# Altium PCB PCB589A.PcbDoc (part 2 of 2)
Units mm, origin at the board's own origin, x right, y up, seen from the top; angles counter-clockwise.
Board outline 111 x 86 mm, 2 copper layers (Top Layer, Top, Bottom Layer, Bottom); 127 components, 84 nets, 406 pads, 157 vias.
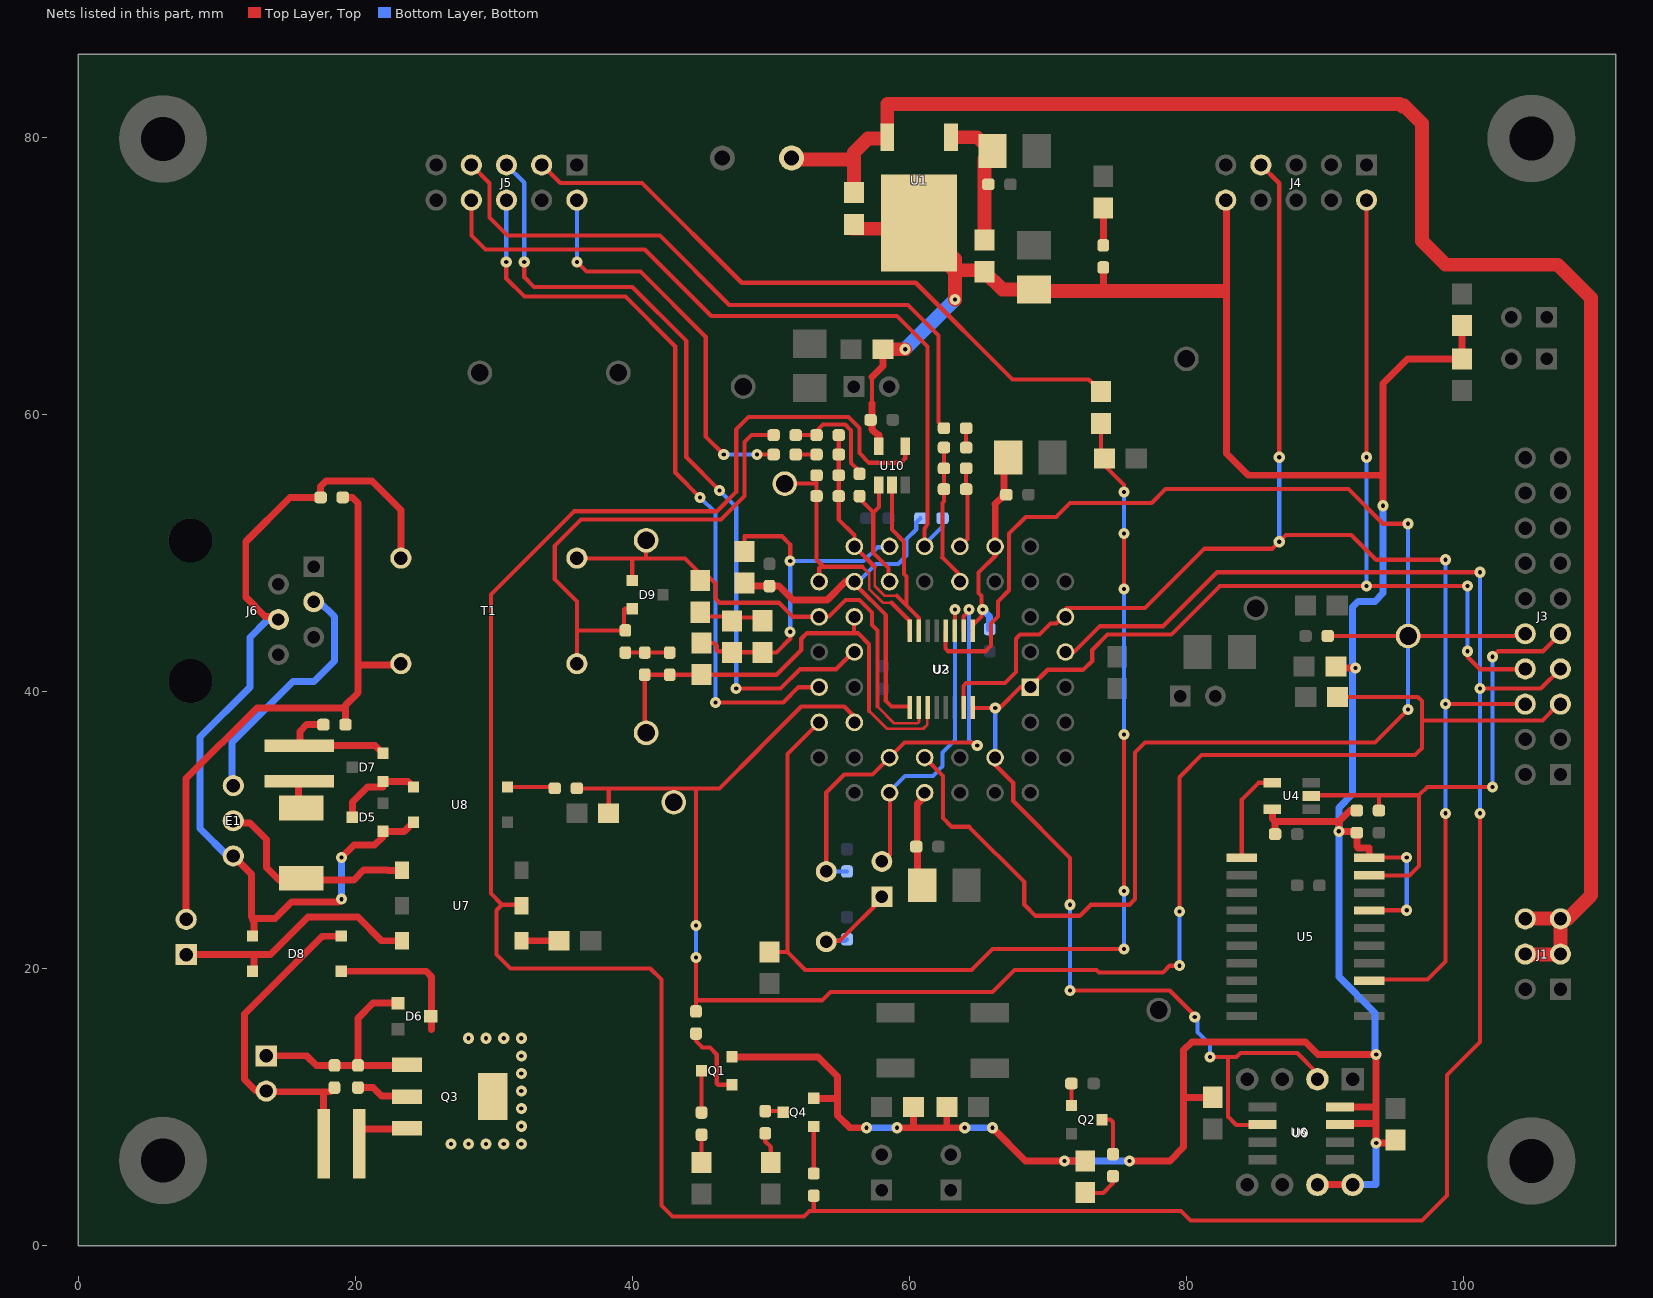
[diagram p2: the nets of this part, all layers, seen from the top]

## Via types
v1: diameter 0.8, hole 0.3, Top Layer, Top to Bottom Layer, Bottom, tented both sides, 154 vias
v2: diameter 0.8, hole 0.3, Top Layer, Top to Bottom Layer, Bottom, 3 vias

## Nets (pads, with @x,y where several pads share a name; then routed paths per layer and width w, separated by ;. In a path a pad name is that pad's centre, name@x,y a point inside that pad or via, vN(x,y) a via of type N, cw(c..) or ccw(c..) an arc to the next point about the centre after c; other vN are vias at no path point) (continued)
HDN: C22.2 R26.1 R27.1 U3.26 | length 83.3
  Top Layer, Top w0.3: R26.1@49.9,21.2 51.2,21.2 ; U3.26@53.49,37.764 51.2,35.474 51.2,21.2 ; C22.2@73.84,56.556 C22.2@74.094,56.81 ; R27.1@73.84,59.35 73.84,57.064 C22.2@74.094,56.81 ; v1(75.5,21.4) 66,21.4 64.5,19.9 52.489,19.9 51.2,21.189 51.2,21.2 ; v1(75.5,25.6) v1(75.5,36.9) ; v1(75.5,47.4) v1(75.5,51.4) ; v1(75.5,54.4) 75.5,54.9 74.1,56.3 74.1,56.804 C22.2@74.094,56.81
  Bottom Layer, Bottom w0.3: v1(75.5,21.4) v1(75.5,25.6) ; v1(75.5,36.9) v1(75.5,47.4) ; v1(75.5,51.4) v1(75.5,54.4)
IRQN: J3.10 R24.2 TP8.TP U2.4 U3.34 | length 127.1
  Top Layer, Top w0.3: U3.34@61.11,35.224 62.43,33.904 62.43,30.854 63.06,30.224 64.32,30.224 68.3,26.244 68.3,24.6 69.1,23.8 72.3,23.8 73.1,24.6 75.9,24.6 76.3,25 76.3,35.6 77,36.3 93.6,36.3 v1(96,38.7) ; U2.4@62.625,44.375 62.6,44.35 62.6,43.1 62.8,42.9 65.5,42.9 65.9,43.3 65.9,44.9 66.4,45.4 66.4,46.5 67.2,47.3 67.2,51.4 68.4,52.6 70.6,52.6 71.6,53.6 77.5,53.6 78.5,54.6 91.7,54.6 94.2,52.1 v1(96,52.1) ; R24.2@90.2,44 TP8.TP@96,44 104.3,44 J3.10@104.46,44.16
  Bottom Layer, Bottom w0.3: v1(96,38.7) TP8.TP@96,44 v1(96,52.1)
MEMPROGN: J3.9 R22.1 U4.2 U5.19 | length 38.5
  Top Layer, Top w0.3: U4.2@89,32.45 89,32.5 93.9,32.5 ; U5.19@93.2,26.73 93.3,26.7 96.1,26.7 96.8,27.4 96.8,32.5 ; R22.1@93.9,31.4 93.9,32.5 ; v1(102.1,33.1) 97.388,33.1 96.8,32.512 96.8,32.5 ; v1(102.1,42.5) 102.5,42.9 105.74,42.9 J3.9@107,44.16 ; 93.9,32.5 96.8,32.5
  Bottom Layer, Bottom w0.3: v1(102.1,33.1) v1(102.1,42.5)
NET00000: Q2.C R9.1 | length 3.2
  Top Layer, Top w0.3: Q2.C@73.91,9.084 73.926,9.1 74.5,9.1 74.7,8.9 R9.1@74.7,6.6
NET00002: D4.2 R9.2 | length 2.8
  Top Layer, Top w0.3: D4.2@72.7,3.814 72.7,3.8 74,3.8 74.7,4.5 R9.2@74.7,5
NET00004: Q2.B R7.2 | length 1.6
  Top Layer, Top w0.3: Q2.B@71.7,10.1 R7.2@71.7,11.7
NET00005: J5.3 R27.2 | length 47.2
  Top Layer, Top w0.3: J5.3@33.46,78 33.5,78 34.8,76.7 40.7,76.7 47.9,69.5 60.465,69.5 67.44,62.525 72.951,62.525 R27.2@73.84,61.636
NET00006: U4.4 U5.1 | length 6.9
  Top Layer, Top w0.3: U5.1@84,28 84,32.2 85.2,33.4 U4.4@86.2,33.4
NET00027: R18.2 U3.16 U10.1 | length 9.2
  Top Layer, Top w0.3: R18.2@56.4,54.1 56.4,53.914 57.4,52.914 ; U10.1@57.8,54.9 57.8,53.314 57.4,52.914 ; U3.16@58.57,47.924 58.5,48 58.5,48.9 57.4,50 57.4,52.914
NET00028: C6.2 C7.1 R11.2 | length 6.6
  Top Layer, Top w0.3: R11.2@47.2,45.086 R11.2@47.2,45.234 ; C7.1@49.4,45.1 49.4,45.264 49.32,45.344 47.31,45.344 R11.2@47.2,45.234 ; C6.2@45.126,45.4 45.42,45.694 45.15,45.964 45,46.114 44.9,46.014 C6.2@44.9,45.714 45.1,45.514 45.1,45.4 C6.2@45.126,45.4 ; C6.2@45.126,45.4 47.1,45.4 47.2,45.3 R11.2@47.2,45.234
NET00155: C16.2 R19.2 R21.1 U3.12 | length 10.3
  Top Layer, Top w0.3: R19.2@62.5,57.6 R21.1@62.5,56.1 C16.2@62.5,54.6 62.5,53.7 62.4,53.6 62.4,49.69 62.38,49.67 63.66,48.39 63.66,47.92 U3.12@63.65,47.924
NET00156: C16.1 R21.2 U3.11 | length 5.9
  Top Layer, Top w0.3: U3.11@63.65,50.46 U3.11@63.65,50.464 63.786,50.6 63.8,50.6 64.2,51 C16.1@64.2,54.6 ; C16.1@64.1,54.6 R21.2@64.1,56.1
NET00157: C12.1 R19.1 | length 1.4
  Top Layer, Top w0.3: R19.1@64.1,57.6 C12.1@64.1,59
NetC1_A: C1.A R2.2 R3.1 U1.1 | length 10.9
  Top Layer, Top w0.5: C1.A@65.4,79 C1.A@65.9,79 ; R2.2@65.425,76.6 R2.2@65.7,76.6
  Top Layer, Top w1: U1.1@63,80 64.9,80 65.9,79 C1.A@66,79 65.425,78.425 65.425,76.6 R3.1@65.425,72.575
NetC10_A: C10.A C11.2 U3.33 | length 7.1
  Top Layer, Top w0.5: C11.2@60.514,28.8 C11.2@60.6,28.8 ; C10.A@60.93,26.014 60.6,26.344 C11.2@60.6,28.8 ; U3.33@61.11,32.684 61.11,32.41 60.57,31.87 60.57,29.04 60.6,29.01 C11.2@60.6,28.8
NetC14_2: C14.2 JP6.1 X1.2 | length 7.3
  Top Layer, Top w0.3: JP6.1@58.02,25.184 58.1,25.104 55,22.004 55,22 X1.2@54.1,22 ; X1.2@54.1,22 54.08,22 X1.2@54,21.92 X1.2@54.1,22
  Bottom Layer, Bottom w0.3: X1.2@54,21.92 54.32,21.92 54.4,22 55.4,22 C14.2@55.5,22.1 ; JP6.1@58,25.1 58.02,25.12 JP6.1@58.02,25.184
NetC24_2: C24.2 R29.1 R31.2 | length 3.2
  Top Layer, Top w0.3: R31.2@39.5,42.8 C24.2@40.9,42.8 R29.1@42.7,42.8
NetC26_1: C26.1 D5.1 D8.3 E1.3 J6.4 T1.6 U8.2 | length 69.1
  Top Layer, Top w0.5: E1.3@11.2,28.12 11.2,28.1 12.52,26.8 12.52,23.73 12.65,23.6 ; D8.3@12.59,22.34 12.7,22.45 12.7,23.6 ; 12.59,23.54 12.65,23.6 ; J6.4@14.46,45.19 14.25,45.4 13.5,45.4 12.1,46.8 12.1,50.8 15.3,54 C26.1@17.5,54 17.5,54.8 17.9,55.2 21.2,55.2 23.3,53.1 T1.6@23.3,49.62 T1.6@23.3,49.6 ; v1(19,25) 18.8,24.8 15.4,24.8 14.2,23.6 12.7,23.6 ; v1(19,28) 19.9,28.9 21.4,28.9 22,29.5 D5.1@22,29.9 23.54,29.9 U8.2@24.2,30.56 ; 12.65,23.6 12.7,23.6
  Bottom Layer, Bottom w0.5: E1.3@11.2,28.12 11.2,28.1 10.8,28.1 8.8,30.1 8.8,36.7 12.4,40.3 12.4,43.9 13.6,45.1 14.5,45.1 J6.4@14.46,45.19 ; v1(19,25) v1(19,28)
NetC26_2: C26.2 C28.1 C29.1 T1.4 | length 44.6
  Top Layer, Top w0.5: C29.1@7.8,23.54 7.8,33.7 12.9,38.8 19.3,38.8 ; C26.2@19.1,54 19.8,54 20.2,53.6 20.2,41.9 ; C28.1@19.3,37.6 19.3,38.8 ; T1.4@23.3,42 23.2,41.9 20.2,41.9 ; 19.3,38.8 19.3,39 20.2,39.9 20.2,41.9
NetC27_1: C27.1 D8.2 R35.2 R37.2 | length 24.9
  Top Layer, Top w0.5: R37.2@17.73,7.34 17.7,7.37 17.7,11.1 ; R35.2@18.5,11.4 18.2,11.1 17.7,11.1 ; D8.2@18.99,22.34 17.703,22.303 ; 17.6,22.3 12,16.7 12,12 12.8,11.2 13.6,11.2 C27.1@13.575,11.15 13.75,11.15 13.8,11.1 17.7,11.1 ; 17.6,22.3 17.703,22.303 ; 17.6,22.3 17.7,22.3 17.703,22.303
NetC27_2: C27.2 D6.1 Q3.1 R34.1 R35.1 | length 17.2
  Top Layer, Top w0.5: C27.2@13.575,13.69 13.6,13.7 16.5,13.7 17.2,13 R35.1@18.5,13 R34.1@20.2,13 ; D6.1@23.1,17.5 21.295,17.5 20.2,16.405 R34.1@20.2,13 ; Q3.1@23.735,13.055 23.68,13 R34.1@20.2,13
NetC28_2: C28.2 D7.2 R36.1 | length 9.3
  Top Layer, Top w0.5: C28.2@17.7,37.6 16.5,37.6 16,37.1 R36.1@16,36.12 ; D7.2@22,35.532 21.432,36.1 16.6,36.1 R36.1@15.96,36.08 R36.1@15.98,36.1 ; R36.1@15.98,36.1 R36.1@16,36.12 ; R36.1@15.98,36.1 16,36.1 R36.1@16,36.12
NetC29_2: C29.2 D8.4 U7.6 | length 18.6
  Top Layer, Top w0.5: C29.2@7.8,21 12.7,21 ; D8.4@12.59,19.8 12.7,19.91 12.7,21 ; U7.6@23.364,22 21.9,22 20.2,23.7 16.6,23.7 13.9,21 12.7,21
NetC30_1: C30.1 E1.2 U7.4 | length 16.5
  Top Layer, Top w0.5: E1.2@11.2,30.66 11.36,30.5 12.4,30.5 13.6,29.3 13.6,27.3 14.5,26.4 C30.1@16.1,26.4 ; C30.1@16.1,26.5 C30.1@16.1,26.4 ; U7.4@23.364,27.08 22.364,27.08 22.344,27.1 20.6,27.1 19.9,26.4 C30.1@16.5,26.4 ; C30.1@16.1,26.4 16.1,26 16.35,26.25 C30.1@16.5,26.4 ; C30.1@16.1,26.4 C30.1@16.5,26.4
NetC30_2: C30.2 R36.2 | length 2.7
  Top Layer, Top w0.5: R36.2@15.96,33.53 15.9,33.5 15.9,31.28 16.1,31.48 C30.2@16.1,31.58
NetC31_1: C31.1 R40.1 | length 1.5
  Top Layer, Top w0.3: C31.1@51.8,57.1 R40.1@53.3,57.1
NetC32_2: C32.2 D9.2 R31.1 T1.1 | length 36.2
  Top Layer, Top w0.3: T1.1@36,42 36,44.4 ; D9.2@40,45.968 39.468,45.968 39.4,45.9 39.4,44.5 R31.1@39.5,44.4 36,44.4 ; C32.2@50.2,58.5 48.6,58.5 48.1,58 48.1,54.1 46.4,52.4 36.3,52.4 34.4,50.5 34.4,48.1 36,46.5 36,44.4
NetD1_1: D1.1 R5.1 | length 2
  Top Layer, Top w0.3: D1.1@45,6 R5.1@45,8
NetD2_1: D2.1 R6.1 | length 2.7
  Top Layer, Top w0.5: R6.1@74,72.2 D2.1@74,74.9
NetD3_1: D3.1 R39.1 | length 2.3
  Top Layer, Top w0.3: R39.1@49.6,8.1 49.6,7.5 50,7.1 D3.1@50,6
NetD5_3: D5.3 D7.1 U8.1 | length 6.5
  Top Layer, Top w0.5: D5.3@19.79,30.916 19.8,30.9 19.8,32 20.9,33.1 22,33.1 D7.1@22,33.5 23.8,33.5 U8.1@24.2,33.1
NetD6_3: D6.3 D8.1 Q3.2 Q3.4 R34.2 | length 14.4
  Top Layer, Top w0.5: D8.1@18.9,19.8 D8.1@18.99,19.8 25.1,19.8 25.5,19.4 D6.3@25.5,16.5 ; R34.2@20.2,11.4 21.3,11.4 21.9,10.8 23.69,10.8 Q3.2@23.735,10.755 ; D6.3@25.45,16.55 D6.3@25.5,16.5 ; 25.5,15.6 D6.3@25.5,16.5
  other v1: 26.91,7.34 28.18,7.34 29.45,7.34 30.72,7.34 31.99,7.34 31.99,8.61 31.99,9.88 31.99,11.15 31.99,12.42 31.99,13.69 28.18,14.96 29.45,14.96 30.72,14.96 31.99,14.96
NetE1_1: E1.1 J6.3 | length 18.2
  Bottom Layer, Bottom w0.5: E1.1@11.2,33.2 11.1,33.3 11.1,36.3 15.5,40.7 17.01,40.7 18.5,42.19 18.5,45.39 17.39,46.5 16.96,46.5 J6.3@17,46.46
NetQ1_1: Q1.1 R4.2 | length 5.7
  Top Layer, Top w0.3: R4.2@44.6,15.3 44.6,14.756 45.056,14.3 45.6,14.3 46.1,13.8 46.1,11.7 46.2,11.6 Q1.1@47.2,11.6
NetQ1_3: Q1.3 R5.2 | length 3
  Top Layer, Top w0.3: Q1.3@44.99,12.616 45,12.6 R5.2@45,9.6
NetQ3_3: Q3.3 R37.1 | length 4.6
  Top Layer, Top w0.5: R37.1@20.28,7.34 20.3,7.36 20.3,8.4 Q3.3@23.79,8.4 ; Q3.3@23.735,8.455 Q3.3@23.79,8.4 ; Q3.3@23.8,8.4 Q3.3@23.79,8.4
NetQ4_1: Q4.1 R8.2 | length 3.4
  Top Layer, Top w0.3: R8.2@53.1,5.2 Q4.1@53.1,8.6
NetQ4_3: Q4.3 R39.2 | length 1.3
  Top Layer, Top w0.3: R39.2@49.6,9.7 50.806,9.7 Q4.3@50.89,9.616
NetR32_2: R32.2 U7.1 | length 2.7
  Top Layer, Top w0.5: U7.1@32,22 R32.2@34.714,22
NetR33_2: R33.2 U8.4 | length 3.4
  Top Layer, Top w0.3: U8.4@31,33.1 34.3,33.1 R33.2@34.4,33
RDATA: J3.8 J4.2 U2.16 U3.1 U3.38 U6.2 U9.2 | length 130.1
  Top Layer, Top w0.3: U2.16@64.575,38.825 64.6,38.8 v1(66.2,38.8) 66.526,38.8 68.03,40.304 U3.1@68.73,40.304 69.99,41.564 72.51,41.564 72.516,41.57 72.57,41.57 73.205,42.205 73.2,42.21 73.2,43 74.3,44.1 78.91,44.1 82.41,47.6 v1(93,47.6) v1(100.3,47.6) ; U3.38@66.19,35.224 66.2,35.214 66.2,34.7 67.5,33.4 67.5,32.084 71.6,27.984 v1(71.6,24.6) ; v1@71.7,18.2 v1@71.7,18.3 ; v1(80.6,16.5) 80.6,16.6 78.8,18.4 v1@71.7,18.4 ; v1(81.7,13.6) 83,13.6 ; U9.2@85.5,8.73 85.4,8.7 83.6,8.7 83,9.3 83,13.6 ; v1(93,56.9) J4.2@93,75.46 ; v1(100.3,42.9) 100.3,42.5 101.2,41.6 104.44,41.6 J3.8@104.46,41.62 ; v1@71.7,18.3 v1(71.6,18.4) v1@71.7,18.4 ; v1@71.7,18.3 v1@71.7,18.4 ; 83,13.6 83.6,13.6 83.9,13.9 88,13.9 U6.2@89.4,12.5 ; U6.2@89.4,12.5 89.46,12.44 U6.2@89.46,12 89.4,12.06 U6.2@89.4,12.5
  Bottom Layer, Bottom w0.3: U3.38@66.19,35.224 66.2,35.2 v1(66.2,38.8) ; v1(71.6,18.4) v1(71.6,24.6) ; v1(80.6,16.5) 80.8,16.3 80.8,15.4 81.7,14.5 v1(81.7,13.6) ; v1(93,47.6) v1(93,56.9) ; v1(100.3,42.9) v1(100.3,47.6)
RDN: C25.2 J3.5 R4.1 R30.1 R33.1 TP11.TP U3.27 | length 130.3
  Top Layer, Top w0.3: R33.1@36,33 38.3,33 ; C25.2@38.286,31.2 38.3,31.214 38.3,33 ; TP11.TP@43,32 43,33 ; R4.1@44.6,16.9 44.6,17.7 ; v1(44.6,20.8) 44.6,17.7 ; v1(44.6,23.1) 44.6,33 ; U3.27@56.03,37.764 56.03,38.17 55.3,38.9 52.2,38.9 49.2,35.9 49.2,35.895 46.305,33 44.6,33 ; v1(79.5,20.2) 78.8,20.2 78.3,19.7 73.7,19.7 73.5,19.9 67.6,19.9 66,18.3 54.3,18.3 53.7,17.7 44.6,17.7 ; v1(79.5,24.1) 79.5,33.8 81.1,35.4 96.5,35.4 97,35.9 97,37.9 ; R30.1@90.9,39.6 96.7,39.6 97,39.3 97,37.9 ; J3.5@107,39.08 106.9,39 106.8,39 105.7,37.9 97,37.9 ; 38.3,33 43,33 ; 43,33 44.6,33
  Bottom Layer, Bottom w0.3: v1(44.6,20.8) v1(44.6,23.1) ; v1(79.5,20.2) v1(79.5,24.1)
RLYDRV: J3.7 R8.1 U3.2 U7.2 U10.4 | length 242.3
  Top Layer, Top w0.3: U7.2@32,24.54 32.06,24.6 30.6,24.6 ; R8.1@53.1,3.6 53.1,2.5 ; U10.4@59.7,57.7 59.7,56.8 59.4,56.5 57.1,56.5 56.4,57.2 56.4,59 55.6,59.8 48.4,59.8 47.5,58.9 47.5,54.4 46.1,53 35.8,53 29.8,47 29.8,25.4 30.6,24.6 ; U3.2@71.27,42.844 71.895,42.844 73.77,44.719 73.789,44.7 78.3,44.7 82.2,48.6 v1(101.2,48.6) ; v1(101.2,31.2) 101.2,14.7 98.8,12.3 98.8,3.6 97,1.8 80.3,1.8 79.6,2.5 53.1,2.5 ; v1(101.2,40.2) 105.58,40.2 J3.7@107,41.62 ; 30.6,24.6 30.2,24.2 30.2,21 31.2,20 41.3,20 42.1,19.2 42.1,2.9 42.9,2.1 52.4,2.1 52.8,2.5 53.1,2.5
  Bottom Layer, Bottom w0.3: v1(101.2,31.2) v1(101.2,40.2) v1(101.2,48.6)
RXA: C7.2 R10.1 R11.1 R14.1 U3.15 | length 26.6
  Top Layer, Top w0.3: R10.1@45,43.5 45.9,43.5 46.1,43.3 46.1,43 46.2,42.9 47,42.9 46.988,42.856 46.98,42.824 47.004,42.8 R11.1@47.2,42.8 ; R14.1@48.1,50.1 48.1,51.2 50.8,51.2 51.4,50.6 v1(51.4,49.4) ; v1(51.4,44.3) 51.4,43.8 50.4,42.8 49.83,42.824 49.82,42.814 C7.2@49.4,42.814 49.276,42.814 49.266,42.824 47.31,42.824 47.286,42.8 R11.1@47.2,42.8 ; R11.1@47.2,42.8 47.16,42.84 47.16,42.85 47.2,42.81 R11.1@47.2,42.8
  Bottom Layer, Bottom w0.3: v1(51.4,44.3) v1(51.4,49.4) 56.7,49.4 57.7,50.4 58.506,50.4 U3.15@58.57,50.464
RXAFB: C13.2 R20.2 TP7.TP U2.8 U3.18 | length 19.7
  Top Layer, Top w0.2: 56.6,49 57.1,48.5 57.1,47.4 58.1,46.4 58.7,46.4
  Top Layer, Top w0.3: TP7.TP@51,55 53.3,55 ; C13.2@53.3,55.6 53.3,55 ; U3.18@53.57,48.004 U3.18@53.49,47.924 53.5,48 53.5,48.9 53.6,49 53.8,49 ; 56.6,49 53.8,49 ; 58.7,46.4 60,45.1 60,44.4 U2.8@60.025,44.375 ; 53.3,55 R20.2@53.3,54.1 53.3,49.5 53.8,49
RXAIN: C32.1 R17.1 R18.1 | length 8.1
  Top Layer, Top w0.3: C32.1@51.8,58.5 R17.1@53.3,58.5 53.4,58.6 53.4,58.9 53.775,59.275 55.37,59.275 55.8,58.845 55.8,56.5 56.4,55.9 R18.1@56.4,55.7
RXALT: C31.2 J5.2 | length 28.6
  Top Layer, Top w0.3: v2(36,71) 36.7,70.3 40.6,70.3 45.3,65.6 45.3,58.4 v2(46.6,57.1) ; v2(49,57.1) C31.2@50.2,57.1
  Bottom Layer, Bottom w0.3: v2(36,71) J5.2@36,75.46 ; v2(46.6,57.1) v2(49,57.1)
RXAN: C13.1 R17.2 R20.1 R40.2 U2.7 U3.17 U10.2 | length 26.2
  Top Layer, Top w0.2: 57.5,48.994 57.5,47.6 58.2,46.9 59.1,46.9
  Top Layer, Top w0.3: R17.2@54.9,58.5 R40.2@54.9,57.1 C13.1@54.9,55.6 R20.1@54.9,54.1 54.9,52.4 56.03,51.27 U3.17@56.03,50.464 57.5,48.994 ; U10.2@58.75,54.9 58.75,51.677 59.625,50.802 59.625,48.475 59.8,48.3 59.8,46.2 ; 59.1,46.9 59.8,46.2 ; U2.7@60.675,44.375 60.7,44.4 60.7,45.3 59.8,46.2
RXB: J5.8 R28.1 U3.13 | length 55.9
  Top Layer, Top w0.3: J5.8@28.38,75.46 28.4,75.44 28.4,72.9 29.4,71.9 40.9,71.9 45.7,67.1 59.1,67.1 61.3,64.9 61.3,52.09 61.1,51.7 U3.13@61.12,50.48 ; U3.13@61.12,50.48 61.12,50.46 61.116,50.464 U3.13@61.11,50.464 61.11,50.47 U3.13@61.12,50.48
  Bottom Layer, Bottom w0.3: U3.13@61.11,50.464 61.11,50.47 61.1,50.5 61.1,50.6 62.4,51.9 R28.1@62.4,52.5
RXBIN: C12.2 J5.7 | length 47.2
  Top Layer, Top w0.3: J5.7@28.38,78 29.7,76.68 29.7,74.2 31,72.9 42,72.9 47,67.9 59.9,67.9 62.1,65.7 62.1,60.614 ; 62.114,60.6 62.1,60.614 ; C12.2@62.5,59 62.1,59.4 62.1,60.614
SCLK: J3.6 J4.7 U2.15 U3.4 U5.13 | length 112.1
  Top Layer, Top w0.3: U2.15@63.925,38.825 63.9,38.85 63.9,40.4 64.1,40.6 66.9,40.6 67.7,41.4 67.7,43.8 68,44.1 69.4,44.1 70.2,44.9 70.6,44.9 71.1,45.4 71.3,45.4 U3.4@71.27,45.384 71.31,45.344 71.346,45.38 71.346,46.015 77.015,46.015 81.3,50.3 86.2,50.3 v1(86.7,50.8) 87.2,51.3 91.9,51.3 93.7,49.5 v1(98.7,49.5) ; J4.7@85.38,78 86.7,76.68 v1(86.7,56.9) ; U5.13@93.2,19.11 93.21,19.1 93.31,19.2 97.4,19.2 98.7,20.5 v1(98.7,31.2) ; v1(98.7,39.1) 104.44,39.1 J3.6@104.46,39.08
  Bottom Layer, Bottom w0.3: v1(86.7,50.8) v1(86.7,56.9) ; v1(98.7,31.2) v1(98.7,39.1) v1(98.7,49.5)
TXA: C24.1 R10.2 R29.2 TP9.TP U2.11 U3.21 | length 34.6
  Top Layer, Top w0.2: 57.1,38.6 58.4,37.3 61,37.3 61.3,37.6 61.3,38.8 U2.11@61.325,38.825
  Top Layer, Top w0.3: TP9.TP@41,37 41,37.5 40.9,37.6 C24.1@40.9,41.2 R29.2@42.7,41.2 44.986,41.2 R10.2@45,41.214 45.1,41.2 50.4,41.2 52.2,43 52.2,43.8 52.6,44.2 56,44.2 ; U3.21@56.03,45.384 56,45.354 56,44.2 ; 57.1,38.6 57.1,43.4 56.3,44.2 56,44.2
TXAN: C6.1 D9.1 T1.3 TP10.TP U2.10 U3.20 | length 39.7
  Top Layer, Top w0.2: 57.7,38.9 58.9,37.7 60.6,37.7 60.7,37.8 60.7,38.8 U2.10@60.675,38.825
  Top Layer, Top w0.3: T1.3@36,49.62 36.2,49.6 40,49.6 ; D9.1@40,48 40,49.6 ; TP10.TP@41,50.3 41,49.6 ; 57.7,38.9 57.7,44.4 57.3,44.8 57.3,45.7 56.4,46.6 55.4,46.6 54.2,45.4 53.6,45.4 U3.20@53.49,45.384 51.616,45.384 50.6,46.4 46.3,46.4 46,46.7 46,47.8 45.4,48.4 C6.1@45,48.4 ; 40,49.6 41,49.6 ; 41,49.6 43.8,49.6 44.9,48.5 C6.1@44.9,48.3 ; C6.1@44.9,48.3 C6.1@44.9,48 45.06,48 45.18,48.12 45.28,48.12 45.15,48.25 C6.1@45,48.4 ; C6.1@44.9,48.3 C6.1@45,48.4
TXB: J5.6 U3.24 | length 54.7
  Top Layer, Top w0.3: v1(30.9,71) 30.9,69.809 32.209,68.5 39.5,68.5 43.1,64.9 43.1,55.8 v1(44.9,54) ; v1(46,39.2) 50.9,39.2 52.004,40.304 U3.24@53.49,40.304
  Bottom Layer, Bottom w0.3: v1(30.9,71) 30.9,75.4 J5.6@30.92,75.46 ; v1(44.9,54) 46,52.9 v1(46,39.2)
TXBN: J5.5 U3.23 | length 58.6
  Top Layer, Top w0.3: v1(32.2,71) 32.2,69.9 32.9,69.2 40,69.2 43.9,65.3 43.9,56.9 v1(46.3,54.5) ; v1(47.5,40.2) 50.7,40.2 52.1,41.6 54.7,41.6 56,42.9 56,42.874 U3.23@56.03,42.844 56.05,42.824 U3.23@56.13,42.824
  Bottom Layer, Bottom w0.3: J5.5@30.92,78 32.2,76.72 v1(32.2,71) ; v1(46.3,54.5) 47.5,53.3 v1(47.5,40.2)
VBIAS: C5.2 R14.2 R28.2 U2.9 U3.19 | length 28.4
  Top Layer, Top w0.3: U3.19@55.395,47.924 55.4,47.9 U3.19@55.424,47.924 ; U3.19@56.03,47.924 56.03,47.57 56.1,47.64 56.1,47.7 58.3,45.5 58.3,39.3 58.7,38.9 59.95,38.9 U2.9@60.025,38.825
  Top Layer, Top w0.5: R14.2@48.1,47.814 48.314,47.6 C5.2@49.9,47.6 50.586,47.614 51.6,46.6 52.3,46.6 52.35,46.604 54.075,46.604 U3.19@55.395,47.924 ; U3.19@55.424,47.924 U3.19@56.03,47.924
  Bottom Layer, Bottom w0.3: U3.19@56.03,47.924 56.324,47.924 57.6,49.2 59.2,49.2 59.8,49.8 59.8,51 60.5,51.7 60.5,52.2 R28.2@60.8,52.5
VDD: C2.A C19.1 C20.1 C23.2 C33.2 D4.1 J4.10 L1.2 L2.2 Q1.2 Q4.2 R1.2 R3.2 R6.2 R12.1 R13.1 R15.2 R16.2 R22.2 R25.1 U1.2 U4.5 U5.17 U5.20 U6.7 U6.8 U9.7 U9.8 U10.5 | length 260.8
  Top Layer, Top w0.3: 57.3,60.8 57.3,62.7 ; U5.17@93.2,24.19 93.21,24.2 v1(95.9,24.2) ; U5.20@93.2,28 v1(95.9,28)
  Top Layer, Top w0.5: Q1.2@47.2,13.632 47.2,13.6 53.4,13.6 54.8,12.2 54.8,10.6 ; Q4.2@53.1,10.632 53.132,10.6 54.8,10.6 ; v1(56.9,8.5) 55.7,8.5 54.8,9.4 54.8,10.6 ; C33.2@57.2,59.6 57.3,59.6 57.3,60.8 ; 57.3,58.9 57.3,58.898 ; 57.3,62.7 58.086,63.486 L2.2@58.086,64.7 ; C33.2@57.302,59.599 57.3,58.898 ; U10.5@57.8,57.7 57.8,58.5 57.3,58.898 ; v1(59.1,8.5) 60.3,8.5 ; R15.2@60.286,10 60.3,9.986 60.3,8.5 ; R16.2@62.714,10 62.7,9.986 62.7,8.6 62.6,8.5 ; v1(64,8.5) 62.6,8.5 ; v1(66,8.5) 68.4,6.1 v1(71.2,6.1) D4.1@72.7,6.1 ; 74,68.9 R6.2@74,70.6 ; v1(75.9,6.1) 78.8,6.1 79.8,7.1 79.8,10.7 ; R25.1@81.9,10.7 79.8,10.7 ; 82.6,68.9 82.9,68.9 ; J4.10@82.84,75.46 83,75.3 82.9,75.2 82.9,68.9 ; U4.5@86.2,31.5 86.2,30.8 86.4,30.6 ; C20.1@86.4,29.7 86.4,30.6 ; U6.7@89.46,4.38 89.48,4.4 92,4.4 U6.8@92,4.38 ; L1.2@90.786,41.8 90.886,41.7 v1(92.2,41.7) ; U9.7@91.088,8.73 91.158,8.8 93.7,8.8 ; U9.8@91.088,10 93.7,10 ; R22.2@92.3,31.4 91.8,31.4 91,30.6 ; U5.20@93.2,28 93.2,28.7 92.4,28.7 92.3,28.8 C19.1@92.3,29.8 92.2,29.9 v1(91,29.9) 91,30.6 ; v1(94.2,53.4) 94.2,55.6 ; C23.2@95.1,7.614 95.1,7.6 94.9,7.4 v1(93.7,7.4) 93.7,8.8 ; R12.1@99.9,66.4 R13.1@99.9,64 ; R13.1@100,64 R13.1@99.9,64 ; 60.3,8.5 62.6,8.5 ; 79.8,10.7 79.8,14.1 80.4,14.7 88.6,14.7 89.5,13.8 v1(93.7,13.8) 93.7,10 ; 82.9,68.9 82.9,57.183 84.483,55.6 94.2,55.6 ; 86.4,30.6 91,30.6 ; 93.7,8.8 93.7,10 ; 94.2,55.6 94.2,62.231 95.969,64 R13.1@99.9,64
  Top Layer, Top w1: R1.2@56,73.714 56,73.5 55.9,73.4 U1.2@61,73.4 ; L2.2@58.086,64.7 v1(59.7,64.7) ; v1(63.3,68.3) U1.2@63.3,70.4 ; 82.6,68.9 74,68.9 69.1,68.9 C2.A@69,69 66.714,69 R3.2@65.425,70.289 65.425,70.035 65.06,70.4 U1.2@63.3,70.4 ; U1.2@61,73.4 U1.2@61,73.5 ; U1.2@61,73.4 U1.2@61.1,73.4 ; U1.2@61,73.4 61,72.6 63.2,70.4 U1.2@63.3,70.4 ; U1.2@61,73.5 U1.2@61,75.04 ; U1.2@61,73.5 U1.2@60.7,73.8 60.7,74.74 U1.2@61,75.04 ; U1.2@61,73.5 U1.2@61.1,73.4 ; U1.2@61,75.04 61.615,74.425 61.615,73.4 U1.2@61.1,73.4 ; U1.2@61.1,73.4 63.3,71.2 U1.2@63.3,70.4
  Bottom Layer, Bottom w0.3: v1(95.9,24.2) v1(95.9,28)
  Bottom Layer, Bottom w0.5: v1(56.9,8.5) v1(59.1,8.5) ; v1(64,8.5) v1(66,8.5) ; v1(71.2,6.1) v1(75.9,6.1) ; U6.8@92,4.38 92.22,4.38 92.2,4.4 93.7,4.4 v1(93.7,7.4) ; v1(93.7,13.8) 93.6,13.9 93.6,16.8 91,19.4 v1(91,29.9) 91,31.6 92,32.6 92,41.5 v1(92.2,41.7) 92,41.9 92,46.1 92.4,46.5 93.6,46.5 94.2,47.1 v1(94.2,53.4)
  Bottom Layer, Bottom w1: v1(59.7,64.7) v1(63.3,68.3)
VDEC: C8.2 C9.A C34.2 U2.1 U3.9 | length 15.5
  Top Layer, Top w0.3: U2.1@64.575,44.375 64.6,44.4 64.6,44.8 65.2,45.4 65.2,46.9 65,47.1 65,48.574 66.2,49.774 U3.9@66.2,49.9
  Top Layer, Top w0.5: U3.9@66.19,50.464 U3.9@66.2,50.474 ; U3.9@66.2,49.9 U3.9@66.2,50.474 ; C8.2@66.714,54.2 C8.2@66.796,54.2 ; C9.A@67.14,56.874 66.84,56.054 C8.2@66.84,54.164 ; U3.9@66.2,50.474 66.2,53.504 66.19,53.514 66.795,54.119 C8.2@66.84,54.164 ; C8.2@66.796,54.2 C8.2@66.804,54.2 ; C8.2@66.796,54.2 66.8,54.204 C8.2@66.804,54.2 ; C8.2@66.804,54.2 C8.2@66.84,54.164
  Bottom Layer, Bottom w0.5: v1@65.25,45.95 v1(65.3,45.9) 65.8,45.4 C34.2@65.8,44.5
VIN: J1.3 J1.4 J1.5 J1.6 J2.2 R1.1 U1.3 | length 127.8
  Top Layer, Top w1: J2.2@51.88,78.3 51.98,78.4 56,78.4 ; R1.1@56,76 56,78.4 ; J1.4@104.46,21.04 104.5,21 107,21 J1.3@107,21.04 J1.5@107,23.58 ; 56,78.4 56,78.9 57,79.9 58.4,79.9 58.4,82.4 95.4,82.4 95.6,82.2 95.7,82.3 97,81 97,72.5 98.7,70.8 106.8,70.8 109.2,68.4 109.2,25.28 107.5,23.58 J1.5@107,23.58 ; J1.6@104.5,23.6 104.48,23.6 J1.6@104.46,23.58 J1.6@104.5,23.6 ; J1.6@104.5,23.6 107,23.6 J1.5@107,23.58
XTAL: JP6.2 U2.3 U3.31 | length 23.2
  Top Layer, Top w0.3: JP6.2@58.02,27.724 58,27.7 58.1,27.7 58.6,28.2 58.6,32.6 U3.31@58.57,32.684 ; U2.3@63.275,44.375 63.3,44.4 v1(63.3,45.9)
  Bottom Layer, Bottom w0.3: U3.31@58.57,32.684 58.6,32.714 58.6,32.8 59.7,33.9 61.7,33.9 62.4,34.6 62.4,35.6 63.3,36.5 v1(63.3,45.9)
XTALN: C15.2 U2.2 U3.32 X1.1 | length 31.7
  Top Layer, Top w0.3: X1.1@54,27 54,32.7 55.3,34 57.346,34 U3.32@58.57,35.224 59.646,36.3 64.5,36.3 v1(64.9,36.1) ; U2.2@63.925,44.375 63.9,44.4 63.9,45.4 64.3,45.8 v1(64.3,45.9) v1@64.4,46
  Bottom Layer, Bottom w0.3: X1.1@54,27 C15.2@55.5,27 ; v1(64.3,45.9) 64.3,36.5 64.8,36 v1(64.9,36.1)
pads on no net: D5.2 D6.2 D7.3 D9.3 J3.1 J3.15 J3.16 J3.17 J3.18 J3.19 J3.20 J4.9 J5.1 J5.9 J6.1 J6.2 J6.5 J6.6 J6.dummy1 J6.dummy2 SW1.2 SW1.3 U4.1 U5.3 U7.3 U7.5

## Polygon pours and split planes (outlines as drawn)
GND on Top Layer, Top "Top-TP7_0" (solid, remove dead copper, pour order 5): 57,38 57,35.5 68.9,35.5 69,35.6 69,38
NetD6_3 on Top Layer, Top "Top Layer, Top-LNET320" (solid, pour order 2): 34.53,6.07 34.53,16.23 21.83,16.23 21.83,6.07
GND on Bottom Layer, Bottom "Bottom Layer, Bottom-GND" (solid, remove dead copper, pour order 6): 20,59 26,59 28,57 28,21 30,19 40,19 40,3 108,3 108,82 20,82
NetD6_3 on Bottom Layer, Bottom "Bottom Layer, Bottom-LNET320" (solid, pour order 4): 35.8,3.53 35.8,16 25.7,16 25.7,17.5 12.94,17.5 12.94,3.53

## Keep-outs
Keep-Out Layer, Board:
  the board outline again, w0.127

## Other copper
Top Layer, Top:
  text "http://www.cmlmicro.com" at 12,81.9 h3
Bottom Layer, Bottom:
  text ".AABoardName" at 18,70.1 h4

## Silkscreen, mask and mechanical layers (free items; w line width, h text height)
Top Overlay, Top Silk:
  region: 2.1,64 14.1,64 14.1,66 24.1,66 24.1,59.5 2.1,59.5
  region: 28.5,71.5 28.5,67 16,67 16,71.5
  lines w0.254: 1.6,59 24.6,59 ; 6.6,56.5 6.6,59 ; 8.6,56.5 8.6,59 ; 10.6,56.5 10.6,59 ; 12.6,56.5 12.6,59 ; 14.6,56.5 14.6,59 ; 16.6,56.5 16.6,59 ; 18.6,56.5 18.6,59 ; 20.6,56.5 20.6,59 ; 22.6,56.5 22.6,59 ; 83.1,10.4 83.3,10.4 ; 92.3,5.7 93.2,5.7 ; 92.3,10.6 93.2,10.6 ; 1.6,56.5 24.6,56.5 24.6,66.5 1.6,66.5 1.6,56.5
  lines w0.305: 86.26,69.322 86.26,69.64 ccw(c85.943,69.64) 85.943,69.957 83.72,69.957 ccw(c83.72,69.64) 83.403,69.64 83.403,68.687 ccw(c83.72,68.687) 83.72,68.37 87.848,68.37 ccw(c87.848,68.687) 88.165,68.687 88.165,69.957 cw(c88.8,69.957) 88.8,70.592 90.388,70.592 cw(c90.388,69.957) 91.023,69.957 91.023,68.687 ccw(c91.34,68.687) 91.34,68.37 91.658,68.37 ccw(c91.658,68.687) 91.975,68.687 91.975,69.957 cw(c92.61,69.957) 92.61,70.592 94.198,70.592 cw(c94.198,69.957) 94.833,69.957 94.833,66.782 cw(c94.198,66.782) 94.198,66.147 83.72,66.147 ccw(c83.72,65.83) 83.403,65.83 83.403,64.56 ccw(c83.72,64.56) 83.72,64.242 93.88,64.242 ccw(c93.88,64.56) 94.198,64.56 94.198,64.877 ; 86.895,69.322 86.895,69.957 ccw(c86.26,69.957) 86.26,70.592 83.403,70.592 ccw(c83.403,69.957) 82.768,69.957 82.768,68.37 ccw(c83.403,68.37) 83.403,67.735 88.165,67.735 ccw(c88.165,68.37) 88.8,68.37 88.8,69.64 cw(c89.118,69.64) 89.118,69.957 90.07,69.957 cw(c90.07,69.64) 90.388,69.64 90.388,68.37 ccw(c91.023,68.37) 91.023,67.735 91.975,67.735 ccw(c91.975,68.37) 92.61,68.37 92.61,69.64 cw(c92.928,69.64) 92.928,69.957 93.88,69.957 cw(c93.88,69.64) 94.198,69.64 94.198,67.1 cw(c93.88,67.1) 93.88,66.782 83.403,66.782 ccw(c83.403,66.147) 82.768,66.147 82.768,64.242 ccw(c83.403,64.242) 83.403,63.607 94.198,63.607 ccw(c94.198,64.242) 94.833,64.242 94.833,64.877
  text "GND" at 43.1,69.6 h2.5
  text "VIN" at 50.1,69.6 h2.5
  text ".AAProductName" at 1.7,67.5 h4
  text "Serial Number" at 2.2,64.4 h2
  text "Mod" at 2.4,57.1 h2
  text "1" at 7.183,57.062 h2
  text "2" at 9.183,57.062 h2
  text "3" at 11.183,57.062 h2
  text "4" at 13.183,57.062 h2
  text "5" at 15.183,57.062 h2
  text "6" at 17.183,57.062 h2
  text "7" at 19.183,57.062 h2
  text "8" at 21.183,57.062 h2
  text "9" at 23.183,57.062 h2
Mechanical 2, Bot Assy:
  lines w0.2: 0.123,0.135 12.123,0.135 12.123,12.135 0.123,12.135 0.123,0.135 ; 0.123,73.883 12.123,73.883 12.123,85.883 0.123,85.883 0.123,73.883 ; 98.897,0.11 110.897,0.11 110.897,12.11 98.897,12.11 98.897,0.11 ; 98.897,73.91 110.897,73.91 110.897,85.91 98.897,85.91 98.897,73.91
Mechanical 3, CutOut:
  lines w2: -1,58 -1,-1 22,-1 ; -1,62 -1,87 22,87 ; 26,-1 83,-1 ; 26,87 83,87 ; 87,-1 112,-1 112,27 ; 87,87 112,87 112,31
Title:
  drawing of 312 lines, arcs and shapes, not listed
  text "1" at -14.314,102.512 h2.6
  text "2" at 34.501,102.512 h2.6
  text "3" at 84.316,102.512 h2.6
  text "4" at 134.131,102.512 h2.6
  text "A" at 156.662,86.175 h2.6
  text "A" at -37.648,86.048 h2.6
  text "B" at 156.662,48.655 h2.6
  text "B" at -37.648,48.528 h2.6
  text "C" at 156.662,11.135 h2.6
  text "C" at -37.648,11.008 h2.6
  text "ENGINEER:" at 68.094,-11.074 h2.6
  text "TITLE:" at -7.471,-11.201 h2.6
  text "P.B." at 81.683,-13.868 h3
  text ".VariantName" at -1.6,-16 h3
  text "PCB DESIGNER:" at 68.094,-18.694 h2.6
  text ".Printout_Name" at -1.4,-19.5 h3
  text "P.B." at 81.683,-21.869 h3
  text "PART NO.:" at -7.598,-26.314 h2.6
  text "DATE:" at 68.221,-26.314 h2.6
  text "D" at 156.662,-26.385 h2.6
  text "D" at -37.648,-26.512 h2.6
  text "REV:" at 45.361,-26.568 h2.6
  text "Oval Park, Langford" at 108.353,-28.092 h2.6
  text "EB0302" at 12.802,-28.254 h3
  text "01/08/2014" at 81.302,-28.854 h3
  text "A01" at 54.759,-29.616 h3
  text "Maldon, Essex" at 108.353,-30.632 h2.6
  text "CM9 6WG" at 108.353,-33.172 h2.6
  text "DWG NO:" at -7.598,-33.807 h2.6
  text "FILE NAME:" at 68.221,-33.934 h2.6
  text "SCALE:" at 45.488,-34.061 h2.6
  text "England" at 108.353,-35.712 h2.6
  text ".Pcb_File_Name_No_Path" at 73.936,-37.109 h2.6
  text "1" at -14.441,-42.776 h2.6
  text "2" at 34.374,-42.776 h2.6
  text "3" at 84.189,-42.776 h2.6
  text "4" at 134.004,-42.776 h2.6
TitleM:
  drawing of 304 lines, arcs and shapes, not listed
  text "1" at -16.748,102.206 h2.6
  text "2" at 32.067,102.206 h2.6
  text "3" at 81.882,102.206 h2.6
  text "4" at 131.697,102.206 h2.6
  text "A" at 154.228,85.869 h2.6
  text "A" at -40.082,85.742 h2.6
  text "B" at 154.228,48.349 h2.6
  text "B" at -40.082,48.222 h2.6
  text "C" at 154.228,10.829 h2.6
  text "C" at -40.082,10.702 h2.6
  text "TITLE:" at 124.588,-11.253 h2.6
  text "ENGINEER:" at 49.404,-11.634 h2.6
  text "P.B." at 41.911,-14.809 h3
  text ".VariantName" at 120.9,-16.5 h3
  text "PCB DESIGNER:" at 49.404,-19 h2.6
  text ".Printout_Name" at 120.9,-20.3 h3
  text "P.B." at 41.86,-22.505 h3
  text "D" at 154.228,-26.691 h2.6
  text "DATE:" at 49.404,-26.747 h2.6
  text "D" at -40.082,-26.818 h2.6
  text "PART NO.:" at 102.236,-26.874 h2.6
  text "REV:" at 125.477,-26.874 h2.6
  text "Oval Park, Langford" at 8.256,-28.271 h2.6
  text "EB0302" at 87.76,-29.605 h3
  text "01/08/2014" at 42.673,-29.668 h3
  text "A01" at 119.254,-29.922 h3
  text "Maldon, Essex" at 8.256,-30.811 h2.6
  text "CM9 6WG" at 8.256,-33.351 h2.6
  text "FILE NAME:" at 49.404,-34.367 h2.6
  text "SCALE:" at 125.477,-34.367 h2.6
  text "DWG NO:" at 102.744,-34.494 h2.6
  text "England" at 8.256,-35.891 h2.6
  text ".Pcb_File_Name_No_Path" at 47.753,-37.669 h2.6
  text "1" at -16.875,-43.082 h2.6
  text "2" at 31.94,-43.082 h2.6
  text "3" at 81.755,-43.082 h2.6
  text "4" at 131.57,-43.082 h2.6
BoardLine:
  the board outline again, w0.2

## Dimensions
111,86.2 to 0,86.2 on Mechanical 1, Top Assy
111.25,0 to 111.2,86 on Mechanical 1, Top Assy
